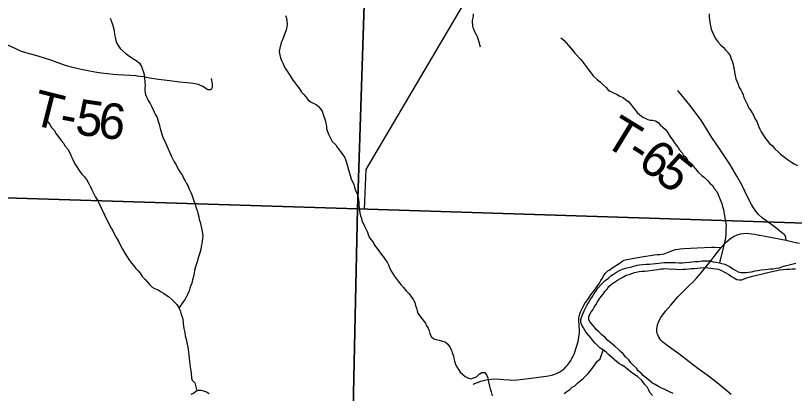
# Model space of a CAD drawing. Extents: x -7.9 to 76.1, y 0 to 22.
# Drawn here: x 6.653 to 7.895, y 14.915 to 15.518 of the extents above; entities that cross this region are included whole.
import ezdxf

# ---------------------------------------------------------------- set-up
doc = ezdxf.new("R2010")
doc.units = 0
for name, color, linetype in [('GM_X_Major_River', 7, 'Continuous'), ('GM_X_Minor_River', 7, 'Continuous'), ('GM_X_Section', 7, 'Continuous'), ('GM_X_State_Route', 7, 'Continuous'), ('GM_X_Township_Road', 7, 'Continuous'), ('GM_X_Township_Road_Text', 7, 'Continuous')]:
    doc.layers.add(name, color=color, linetype=linetype)

msp = doc.modelspace()

# ---------------------------------------------------------------- linework, layer by layer
at = {"layer": 'GM_X_Major_River'}
for points in [[(7.5596, 15.047), (7.5618, 15.0508), (7.564, 15.0554), (7.5666, 15.0596), (7.5692, 15.0646), (7.5729, 15.0699), (7.5755, 15.0745), (7.5789, 15.0787), (7.5811, 15.0826), (7.5882, 15.0906), (7.593, 15.0949), (7.5983, 15.0991), (7.6024, 15.1026), (7.6062, 15.1053), (7.6111, 15.1084), (7.616, 15.1111), (7.6209, 15.1131), (7.6254, 15.1147), (7.6303, 15.1159), (7.6356, 15.1171), (7.6439, 15.1195), (7.6477, 15.1203), (7.6526, 15.1208), (7.6587, 15.1212), (7.6632, 15.1213), (7.6731, 15.1222), (7.6787, 15.123), (7.6825, 15.1234), (7.6871, 15.1239), (7.6958, 15.124), (7.7007, 15.1237), (7.7049, 15.1238), (7.711, 15.1235), (7.7163, 15.1235), (7.7208, 15.124), (7.7273, 15.1244), (7.7314, 15.1249), (7.7367, 15.1253), (7.7416, 15.1254), (7.7477, 15.1266), (7.7557, 15.1267), (7.7602, 15.1264), (7.7655, 15.125), (7.7697, 15.1243), (7.7754, 15.1232), (7.7792, 15.1221), (7.7838, 15.1211), (7.7922, 15.117), (7.7964, 15.114), (7.8014, 15.1111), (7.8052, 15.1088), (7.8094, 15.1081), (7.8132, 15.1078), (7.8177, 15.1079), (7.8215, 15.1083), (7.8264, 15.1091), (7.8321, 15.1104), (7.8363, 15.1112), (7.8419, 15.112), (7.848, 15.1129), (7.8529, 15.1133), (7.8567, 15.1137), (7.8609, 15.1138), (7.8654, 15.1146), (7.8703, 15.1154), (7.8764, 15.1174), (7.8817, 15.119), (7.8862, 15.1202), (7.8907, 15.121), (7.8968, 15.1226)], [(7.597, 15.0001), (7.5931, 15.0042), (7.587, 15.009), (7.5831, 15.0132), (7.5785, 15.0173), (7.5762, 15.021), (7.5724, 15.0248), (7.5693, 15.0285), (7.5673, 15.0323), (7.5669, 15.0365), (7.5684, 15.0403), (7.5702, 15.0441), (7.5732, 15.0483), (7.5758, 15.0525), (7.5784, 15.0564), (7.581, 15.0613), (7.5836, 15.0655), (7.5866, 15.0694), (7.5899, 15.0736), (7.5925, 15.0774), (7.5963, 15.0816), (7.5992, 15.0855), (7.6034, 15.0893), (7.6128, 15.0955), (7.6173, 15.0983), (7.6222, 15.101), (7.6267, 15.1037), (7.6316, 15.1049), (7.6399, 15.1081), (7.6474, 15.1097), (7.652, 15.1101), (7.6562, 15.1102), (7.6607, 15.1106), (7.6645, 15.1111), (7.6683, 15.1119), (7.6728, 15.1123), (7.6766, 15.1127), (7.6819, 15.1136), (7.6861, 15.114), (7.6899, 15.1141), (7.694, 15.1137), (7.6982, 15.1134), (7.7024, 15.1135), (7.7069, 15.1132), (7.7122, 15.1129), (7.7172, 15.1133), (7.721, 15.1134), (7.7266, 15.1138), (7.7304, 15.1142), (7.735, 15.1143), (7.7403, 15.1148), (7.7444, 15.1152), (7.7494, 15.116), (7.757, 15.1154), (7.7615, 15.1147), (7.7653, 15.1144), (7.7699, 15.1137), (7.7737, 15.113), (7.7786, 15.1111), (7.7901, 15.1045), (7.7943, 15.1015), (7.7985, 15.0993), (7.8031, 15.097), (7.8069, 15.0963), (7.8107, 15.096), (7.8148, 15.0976), (7.819, 15.0995), (7.8228, 15.1004), (7.828, 15.1019), (7.8326, 15.1031), (7.8371, 15.104), (7.842, 15.1052), (7.8466, 15.1064), (7.8503, 15.1076), (7.8564, 15.1092), (7.8666, 15.1112), (7.8711, 15.112), (7.8829, 15.113), (7.8867, 15.1134), (7.8912, 15.1135), (7.8965, 15.1135)], [(7.6683, 14.9119), (7.6645, 14.9164), (7.6625, 14.9201), (7.6606, 14.9247), (7.6559, 14.9299), (7.6513, 14.9359), (7.6444, 14.9423), (7.639, 14.9456), (7.6329, 14.9501), (7.6291, 14.9531), (7.6252, 14.9568), (7.6199, 14.9602), (7.6161, 14.9624), (7.6119, 14.9654), (7.6076, 14.9691), (7.5988, 14.9769), (7.5946, 14.9811), (7.5904, 14.984), (7.5854, 14.9874), (7.5773, 14.9952), (7.5735, 14.9997), (7.5704, 15.0039), (7.5669, 15.0076), (7.5634, 15.0117), (7.5607, 15.0159), (7.5584, 15.0196), (7.5557, 15.0242), (7.5545, 15.0283), (7.5544, 15.0332), (7.5559, 15.0378), (7.5596, 15.047)], [(7.7016, 14.915), (7.6967, 14.9172), (7.6925, 14.9194), (7.6871, 14.922), (7.6829, 14.9235), (7.678, 14.9264), (7.6726, 14.9294), (7.6684, 14.9316), (7.6646, 14.9346), (7.6539, 14.9436), (7.6504, 14.9473), (7.6458, 14.9514), (7.6431, 14.9552), (7.6381, 14.9597), (7.6339, 14.9641), (7.6308, 14.9687), (7.6262, 14.9728), (7.6219, 14.978), (7.6173, 14.9821), (7.6139, 14.9859), (7.6085, 14.9907), (7.6027, 14.9952), (7.597, 15.0001)], [(6.9331, 14.9139), (6.9368, 14.9158), (6.9406, 14.9185), (6.9451, 14.9201), (6.9489, 14.9202), (6.9531, 14.9195), (6.9576, 14.9176), (6.9619, 14.915)]]:
    msp.add_lwpolyline(points, dxfattribs=at)
at = {"layer": 'GM_X_Minor_River'}
for points in [[(7.0834, 15.5178), (7.085, 15.5136), (7.0858, 15.5087), (7.0862, 15.5042), (7.0856, 15.4992)], [(7.7587, 15.5203), (7.7591, 15.5154), (7.76, 15.5063), (7.7608, 15.5014), (7.7621, 15.4961), (7.7636, 15.4919), (7.7656, 15.4874), (7.7675, 15.4837), (7.7699, 15.4795), (7.773, 15.475), (7.7776, 15.4705), (7.7814, 15.4671), (7.7849, 15.463), (7.7891, 15.4581), (7.7922, 15.4536), (7.7942, 15.4487), (7.7957, 15.4446), (7.7969, 15.44), (7.7978, 15.4359), (7.7986, 15.4321), (7.7994, 15.4275), (7.8002, 15.4222), (7.8014, 15.4169), (7.8034, 15.4117), (7.8053, 15.4079), (7.8065, 15.403), (7.8092, 15.3992), (7.8116, 15.3947), (7.8128, 15.3909), (7.814, 15.3868), (7.8163, 15.3826), (7.8202, 15.3751), (7.8218, 15.3709), (7.8245, 15.3668), (7.8272, 15.3623), (7.8295, 15.3585), (7.8315, 15.3536), (7.8346, 15.3487), (7.8365, 15.3442), (7.8381, 15.34), (7.8397, 15.3363), (7.8416, 15.3321), (7.8478, 15.3231), (7.8513, 15.3182), (7.8551, 15.3137), (7.8594, 15.3104), (7.8636, 15.3051), (7.869, 15.3002), (7.8724, 15.2965), (7.877, 15.2935), (7.8809, 15.2902), (7.8855, 15.2872), (7.8901, 15.2838), (7.8943, 15.2812), (7.8996, 15.2787)], [(6.8044, 15.5136), (6.8056, 15.509), (6.8072, 15.5049), (6.8099, 15.4962), (6.8107, 15.4924), (6.8112, 15.4875), (6.812, 15.4833), (6.8132, 15.478), (6.8144, 15.4742), (6.8171, 15.4697), (6.8202, 15.4648), (6.829, 15.457), (6.8336, 15.4536), (6.8386, 15.4503), (6.8428, 15.4477), (6.847, 15.4447), (6.8509, 15.4414), (6.854, 15.4365), (6.8559, 15.4316), (6.8571, 15.4274), (6.8583, 15.4236), (6.8588, 15.4187), (6.8596, 15.4115), (6.8597, 15.4062), (6.8594, 15.402), (6.8594, 15.3982), (6.8598, 15.394), (6.861, 15.3903), (6.863, 15.3857), (6.8649, 15.382), (6.8677, 15.3771), (6.87, 15.3733), (6.8739, 15.365), (6.8766, 15.3594), (6.879, 15.3548), (6.8805, 15.3492), (6.8821, 15.3446), (6.8833, 15.3397), (6.8841, 15.3356), (6.8869, 15.3269), (6.8885, 15.3223), (6.8908, 15.3182), (6.8924, 15.3144), (6.8943, 15.3099), (6.9014, 15.294), (6.9064, 15.2842), (6.9092, 15.2794), (6.9115, 15.2748), (6.9138, 15.2711), (6.9165, 15.2666), (6.9193, 15.2624), (6.9212, 15.2583), (6.9235, 15.2541), (6.9259, 15.25), (6.9282, 15.2455), (6.9302, 15.2409), (6.9325, 15.2357), (6.9341, 15.2319), (6.9376, 15.2224), (6.9392, 15.2179), (6.942, 15.2092), (6.9432, 15.2051), (6.9444, 15.2005), (6.9452, 15.1967), (6.946, 15.1926), (6.9476, 15.188), (6.9488, 15.1835), (6.9504, 15.1759), (6.9512, 15.1703), (6.9516, 15.1665), (6.9513, 15.1619), (6.9506, 15.1577), (6.9503, 15.1536), (6.9492, 15.1494), (6.9485, 15.1448), (6.9463, 15.1376), (6.9442, 15.1311), (6.9431, 15.1265), (6.9416, 15.1216), (6.9402, 15.117), (6.9387, 15.1109), (6.938, 15.1071), (6.937, 15.1018), (6.9355, 15.0961), (6.9341, 15.0911), (6.9326, 15.0873), (6.9312, 15.0831), (6.9301, 15.0785), (6.9279, 15.0739), (6.926, 15.0697), (6.9238, 15.0655), (6.9205, 15.0609), (6.9136, 15.0513)], [(7.0856, 15.4992), (7.0845, 15.495), (7.0805, 15.4832), (7.0786, 15.4786), (7.0768, 15.4744), (7.0743, 15.4657), (7.0736, 15.4607), (7.074, 15.4569), (7.0756, 15.4501), (7.0776, 15.4449), (7.0799, 15.4407), (7.0822, 15.4351), (7.0861, 15.429), (7.0888, 15.4245), (7.0919, 15.42), (7.0954, 15.4144), (7.0989, 15.4095), (7.1024, 15.4057), (7.1058, 15.4008), (7.1093, 15.3952), (7.1128, 15.3915), (7.1159, 15.3877), (7.1193, 15.3836), (7.1236, 15.3802), (7.1278, 15.378), (7.1323, 15.3758), (7.1362, 15.3728), (7.1396, 15.3691), (7.142, 15.3649), (7.1436, 15.36), (7.1467, 15.3509), (7.1479, 15.3456), (7.1487, 15.3411), (7.1492, 15.3373), (7.1504, 15.3328), (7.1527, 15.3275), (7.1582, 15.3169), (7.1639, 15.3113), (7.1662, 15.3076), (7.1724, 15.2993), (7.1751, 15.2955), (7.1782, 15.291), (7.1802, 15.285), (7.1818, 15.2797), (7.1842, 15.2714), (7.1854, 15.2665), (7.1866, 15.2627), (7.1885, 15.2566), (7.1909, 15.2521), (7.1925, 15.248), (7.1937, 15.2438), (7.1952, 15.2385), (7.1972, 15.2347), (7.1988, 15.2295), (7.2, 15.2238), (7.2004, 15.22), (7.2005, 15.2154), (7.2009, 15.2105), (7.2014, 15.2067), (7.2022, 15.2029), (7.203, 15.198), (7.2046, 15.1942), (7.2054, 15.1905), (7.2081, 15.1856), (7.2097, 15.1818), (7.2124, 15.1765), (7.2143, 15.1724), (7.2151, 15.1686), (7.2171, 15.1641), (7.2198, 15.1603), (7.2233, 15.1562), (7.2256, 15.1513), (7.2295, 15.1464), (7.2322, 15.1426), (7.236, 15.1374), (7.2395, 15.1333), (7.2426, 15.1287), (7.2457, 15.1246), (7.2476, 15.1201), (7.2496, 15.1159), (7.2516, 15.111), (7.2539, 15.1069), (7.2566, 15.1027), (7.2601, 15.0982), (7.2632, 15.0941), (7.2674, 15.0889), (7.2716, 15.084), (7.2759, 15.0787), (7.2801, 15.0746), (7.284, 15.0697), (7.2871, 15.0648), (7.2898, 15.0599), (7.291, 15.0554), (7.2926, 15.0513), (7.2934, 15.0467), (7.2946, 15.0429), (7.2973, 15.0392), (7.3023, 15.0324), (7.3069, 15.0272), (7.3085, 15.023), (7.3112, 15.0193)], [(7.5226, 15.4821), (7.5272, 15.4784), (7.531, 15.4743), (7.5345, 15.4698), (7.538, 15.466), (7.5411, 15.4623), (7.5449, 15.4578), (7.5545, 15.4477), (7.5596, 15.4405), (7.5646, 15.4341), (7.5688, 15.4281), (7.5746, 15.421), (7.5804, 15.4154), (7.5854, 15.4117), (7.5892, 15.4075), (7.5946, 15.4027), (7.5984, 15.3982), (7.6122, 15.3915), (7.6164, 15.3889), (7.6217, 15.3867), (7.6259, 15.3834), (7.6301, 15.3804), (7.6402, 15.368), (7.644, 15.3631), (7.6482, 15.3594), (7.6532, 15.3557), (7.657, 15.3538), (7.6609, 15.352), (7.6647, 15.3509), (7.6688, 15.3506), (7.6734, 15.3495), (7.6776, 15.3469), (7.6811, 15.3428), (7.6849, 15.3394), (7.6891, 15.3361), (7.6922, 15.3316), (7.6961, 15.3252), (7.7004, 15.3195), (7.7038, 15.3146), (7.7062, 15.3109), (7.7096, 15.3071), (7.7116, 15.3034), (7.7158, 15.2989), (7.7181, 15.2947), (7.722, 15.2917), (7.7251, 15.2861), (7.7297, 15.2816), (7.7335, 15.2775), (7.737, 15.2734), (7.7412, 15.2681), (7.747, 15.2625), (7.7512, 15.2591), (7.7562, 15.2546), (7.7597, 15.2505), (7.7643, 15.2464), (7.767, 15.2419), (7.7709, 15.237), (7.7728, 15.2332), (7.7775, 15.2219), (7.7791, 15.2178), (7.7803, 15.2132), (7.7815, 15.2083), (7.7823, 15.2045), (7.7835, 15.1981), (7.7856, 15.1867), (7.786, 15.183), (7.7857, 15.1788), (7.7857, 15.1742), (7.7854, 15.17), (7.7848, 15.1621), (7.7841, 15.1583), (7.7826, 15.1537), (7.7754, 15.1232)], [(6.7023, 15.352), (6.7054, 15.3475), (6.7081, 15.3438), (6.7108, 15.3392), (6.7147, 15.3347), (6.7178, 15.3291), (6.722, 15.3242), (6.7263, 15.3182), (6.7301, 15.3137), (6.7321, 15.3099), (6.7367, 15.3043), (6.741, 15.2964), (6.7425, 15.2922), (6.7445, 15.2881), (6.748, 15.2813), (6.7519, 15.2749), (6.7546, 15.2704), (6.7588, 15.2648), (6.7631, 15.2603), (6.7662, 15.2561), (6.7708, 15.2486), (6.7728, 15.2445), (6.7747, 15.2399), (6.7782, 15.2335), (6.7809, 15.2279), (6.7837, 15.2234), (6.786, 15.2192), (6.7915, 15.2072), (6.7934, 15.2034), (6.7957, 15.1985), (6.7989, 15.1925), (6.8028, 15.1842), (6.8059, 15.1785), (6.8082, 15.1744), (6.8105, 15.1695), (6.8148, 15.1623), (6.8179, 15.157), (6.8203, 15.1518), (6.8238, 15.145), (6.8276, 15.1386), (6.8311, 15.1329), (6.8339, 15.1284), (6.8389, 15.1224), (6.8419, 15.1187), (6.845, 15.1145), (6.8485, 15.1108), (6.852, 15.1067), (6.8554, 15.1018), (6.8601, 15.0965), (6.8639, 15.0924), (6.8674, 15.0883), (6.8712, 15.0845), (6.875, 15.0823), (6.8804, 15.0801), (6.8854, 15.0771), (6.8892, 15.0749), (6.893, 15.0723), (6.8972, 15.0697), (6.9018, 15.0656), (6.9064, 15.0611), (6.9103, 15.057), (6.913, 15.0525), (6.9157, 15.0472), (6.9169, 15.0431), (6.9181, 15.0385), (6.9197, 15.034), (6.9205, 15.0268), (6.921, 15.0226), (6.9218, 15.0188), (6.923, 15.012), (6.9238, 15.0071), (6.9254, 15.0014), (6.927, 14.9939), (6.9283, 14.9859), (6.9291, 14.9802), (6.9296, 14.9761), (6.93, 14.9711), (6.9308, 14.9658), (6.9317, 14.9575), (6.9325, 14.9514), (6.933, 14.9476), (6.9338, 14.9393), (6.935, 14.9363), (6.9389, 14.9318), (6.9423, 14.9191)], [(7.3112, 15.0193), (7.3128, 15.0147), (7.3136, 15.0106), (7.3159, 15.006), (7.3198, 15.0023), (7.3236, 15.0012), (7.3285, 15.0001), (7.3338, 14.9987), (7.338, 14.9972), (7.3426, 14.9935), (7.3457, 14.989), (7.3481, 14.9841), (7.3493, 14.9796), (7.3512, 14.975), (7.352, 14.9709), (7.3532, 14.9663), (7.3548, 14.9614), (7.3568, 14.9577), (7.3591, 14.9535), (7.3618, 14.949), (7.366, 14.9453), (7.3702, 14.9419), (7.3752, 14.9397), (7.379, 14.9386), (7.3839, 14.9398), (7.3881, 14.9418), (7.3922, 14.946), (7.3963, 14.9487), (7.4013, 14.9484), (7.4047, 14.9439), (7.4059, 14.9401), (7.4071, 14.9337), (7.4087, 14.9269), (7.4099, 14.9227), (7.4115, 14.9178), (7.4131, 14.9114)], [(7.528, 14.9149), (7.5321, 14.918), (7.5366, 14.9214), (7.5404, 14.9249), (7.5445, 14.9272), (7.549, 14.9315), (7.5527, 14.9349), (7.558, 14.9388), (7.5658, 14.9469), (7.574, 14.9569), (7.577, 14.9618), (7.5811, 14.9665), (7.5849, 14.9703), (7.5901, 14.9842)]]:
    msp.add_lwpolyline(points, dxfattribs=at)
at = {"layer": 'GM_X_Section'}
for points in [[(6.2227, 16.2415), (7.2312, 16.2186), (7.1984, 15.2096), (6.1958, 15.241)], [(8.2558, 16.1845), (8.2275, 15.1763), (7.1984, 15.2096), (7.2312, 16.2186)], [(7.1984, 15.2096), (7.1768, 14.2053), (6.1699, 14.2253), (6.1958, 15.241)], [(7.1984, 15.2096), (8.2275, 15.1763), (8.1994, 14.1795), (7.1768, 14.2053)]]:
    msp.add_lwpolyline(points, close=True, dxfattribs=at)
at = {"layer": 'GM_X_State_Route'}
for points in [[(7.7266, 15.0867), (7.7332, 15.093), (7.7386, 15.0988), (7.7461, 15.1074), (7.7526, 15.1156), (7.7618, 15.1269), (7.7702, 15.1375), (7.7782, 15.1476), (7.7825, 15.1527), (7.7866, 15.157), (7.7907, 15.1607), (7.7944, 15.1633), (7.7978, 15.1652), (7.8037, 15.1677), (7.8089, 15.1693), (7.8135, 15.1701), (7.8181, 15.1704), (7.8222, 15.1703), (7.8267, 15.1698), (7.8318, 15.1689), (7.8384, 15.1676), (7.8394, 15.1674)], [(7.8394, 15.1674), (7.8509, 15.1651), (7.8816, 15.1592), (7.8946, 15.1565), (7.9031, 15.1547)], [(7.7937, 14.9136), (7.7837, 14.9217), (7.7688, 14.9342), (7.7557, 14.9441), (7.7408, 14.955), (7.7272, 14.9656), (7.7103, 14.9784), (7.6919, 14.9914), (7.6851, 14.9969), (7.6823, 14.9995), (7.6802, 15.002), (7.6786, 15.0049), (7.6768, 15.0085), (7.676, 15.0107), (7.6755, 15.0135), (7.6754, 15.0168), (7.6759, 15.0207), (7.6767, 15.0243), (7.678, 15.0286), (7.6798, 15.0324), (7.6819, 15.0361), (7.6844, 15.0397), (7.6898, 15.0467), (7.6976, 15.0559), (7.7089, 15.0689), (7.7135, 15.0737), (7.7193, 15.0796), (7.7266, 15.0867)]]:
    msp.add_lwpolyline(points, dxfattribs=at)
at = {"layer": 'GM_X_Township_Road'}
for points in [[(7.2095, 15.2084), (7.2122, 15.2722), (7.3793, 15.5566)], [(7.3944, 15.4671), (7.3921, 15.4753), (7.3907, 15.4804), (7.3896, 15.4834), (7.3881, 15.4868), (7.3849, 15.4926), (7.3836, 15.4956), (7.3828, 15.4981), (7.3823, 15.5004), (7.382, 15.5027), (7.3818, 15.5064), (7.3819, 15.5091), (7.3824, 15.5125), (7.3831, 15.5167), (7.3832, 15.5203)], [(6.6405, 15.4707), (6.6524, 15.4653), (6.6576, 15.4628), (6.6623, 15.4609), (6.6674, 15.4592), (6.6712, 15.4581), (6.6886, 15.4532), (6.7022, 15.4492), (6.7107, 15.4463), (6.729, 15.4397), (6.7341, 15.4381), (6.7421, 15.4359), (6.7579, 15.4323), (6.771, 15.4296), (6.783, 15.4274), (6.7901, 15.4263), (6.8002, 15.425), (6.8085, 15.4242), (6.8165, 15.4235), (6.8356, 15.4226), (6.8448, 15.4218)], [(6.8448, 15.4218), (6.8469, 15.4216), (6.8573, 15.4202), (6.8669, 15.4185), (6.881, 15.4163), (6.899, 15.4138), (6.9148, 15.4121), (6.9271, 15.4107), (6.9324, 15.4103), (6.9363, 15.4099), (6.9395, 15.4094), (6.942, 15.4089), (6.9446, 15.408), (6.9478, 15.4068), (6.9517, 15.405), (6.9547, 15.4032), (6.9588, 15.4004), (6.9599, 15.3998), (6.962, 15.3994), (6.9639, 15.3997), (6.9654, 15.4005), (6.9664, 15.4014), (6.967, 15.4034), (6.9673, 15.4061), (6.967, 15.4089), (6.9659, 15.4174)], [(7.8816, 15.1592), (7.8812, 15.1639), (7.8801, 15.1668), (7.8784, 15.1687), (7.8717, 15.1739), (7.8648, 15.1795), (7.8515, 15.1892), (7.8433, 15.1951), (7.8374, 15.2005), (7.8333, 15.2055), (7.8294, 15.2109), (7.8263, 15.2164), (7.8196, 15.2296), (7.811, 15.2478), (7.8032, 15.2617), (7.792, 15.2808), (7.7771, 15.3027), (7.7632, 15.3233), (7.7459, 15.3506), (7.7281, 15.3745), (7.7087, 15.398)], [(7.3829, 14.9301), (7.3951, 14.9345), (7.4034, 14.9368), (7.4072, 14.9375), (7.412, 14.9381), (7.4157, 14.9385), (7.426, 14.938), (7.4316, 14.9375), (7.44, 14.9367), (7.4432, 14.9365), (7.4531, 14.9368), (7.4709, 14.9387), (7.4911, 14.9414), (7.5028, 14.9434), (7.5097, 14.9449), (7.5127, 14.9458), (7.5158, 14.947), (7.5189, 14.9485), (7.5218, 14.9502), (7.5246, 14.9521), (7.5276, 14.9546), (7.5306, 14.9574), (7.5331, 14.9603), (7.5362, 14.9642), (7.5385, 14.9678), (7.5401, 14.9706), (7.5417, 14.9734), (7.5435, 14.9775), (7.5481, 14.9908), (7.5499, 14.9978), (7.5514, 15.005), (7.5519, 15.0088), (7.5523, 15.0122), (7.5515, 15.0254), (7.5512, 15.0292), (7.5514, 15.0353), (7.5518, 15.0384), (7.5526, 15.0414), (7.554, 15.0452), (7.5575, 15.0529), (7.5606, 15.0584), (7.5663, 15.0667), (7.5701, 15.0721), (7.5792, 15.0838), (7.5815, 15.087), (7.584, 15.091), (7.5864, 15.095), (7.5888, 15.099), (7.5906, 15.1024), (7.5919, 15.1047), (7.5935, 15.1068), (7.5953, 15.1087), (7.5972, 15.1104), (7.5994, 15.1119), (7.6053, 15.1158), (7.6156, 15.1225), (7.6215, 15.1263), (7.6235, 15.1274), (7.6256, 15.1282), (7.6278, 15.1288), (7.6418, 15.1313), (7.6545, 15.1335), (7.6678, 15.1358), (7.6718, 15.1362), (7.6765, 15.1365), (7.6804, 15.1365), (7.6837, 15.1369), (7.6872, 15.1378), (7.6922, 15.1398), (7.7022, 15.1436), (7.7054, 15.1446), (7.7092, 15.1453), (7.7128, 15.1458), (7.7185, 15.1462), (7.7395, 15.1472), (7.7626, 15.1482), (7.7673, 15.1481), (7.7782, 15.1476)]]:
    msp.add_lwpolyline(points, dxfattribs=at)

# ---------------------------------------------------------------- texts
at = {"layer": 'GM_X_Township_Road_Text'}
for s, rotation, p in [('T', 345.7964, (6.6763, 15.3449)), ('5', 351.6305, (6.7467, 15.3289)), ('6', 353.2907, (6.7831, 15.3236)), ('-', 349.3778, (6.7213, 15.3336)), ('T', 328.4802, (7.5878, 15.3126)), ('-', 326.6639, (7.6236, 15.2907)), ('6', 324.2896, (7.6426, 15.2782)), ('5', 320.9647, (7.6703, 15.2583))]:
    msp.add_text(s, height=0.0568, rotation=rotation, dxfattribs=at).set_placement(p)

doc.saveas('drawing.dxf')
